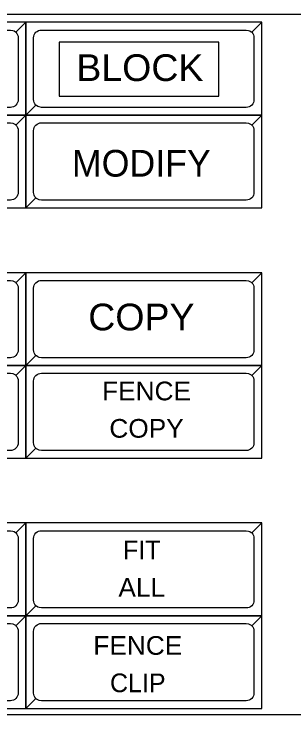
# Model space of a CAD drawing. Extents: x 16898 to 16911.6, y 15837.8 to 15842.
# Drawn here: x 16904.383 to 16905.198, y 15839.972 to 15842.012 of the extents above; entities that cross this region are included whole.
import ezdxf
from ezdxf.enums import TextEntityAlignment as Align

# ---------------------------------------------------------------- set-up
doc = ezdxf.new("R2010")
doc.units = 0
doc.header["$LTSCALE"] = 0.018
for name, color, linetype, lineweight in [('1', 7, 'Continuous', 25), ('2', 7, 'Continuous', 13), ('5', 7, 'Continuous', 13)]:
    doc.layers.add(name, color=color, linetype=linetype, lineweight=lineweight)

msp = doc.modelspace()

# ---------------------------------------------------------------- linework, layer by layer
at = {"layer": '1'}
for points in [[(16897.9955, 15839.9723), (16897.9955, 15842.0124), (16911.4764, 15842.0124), (16911.5674, 15841.9251), (16911.5674, 15840.0599), (16911.4764, 15839.9723)], [(16903.7314, 15841.7183), (16904.4178, 15841.7183), (16904.4178, 15841.9883), (16903.7314, 15841.9883)], [(16903.7314, 15841.7183), (16904.4178, 15841.7183), (16904.4178, 15841.9883), (16904.3887, 15841.9592), (16904.3915, 15841.9558), (16904.3936, 15841.9519), (16904.3948, 15841.9477), (16904.3953, 15841.9433), (16904.3953, 15841.7633), (16904.3948, 15841.7589), (16904.3936, 15841.7547), (16904.3915, 15841.7508), (16904.3887, 15841.7474), (16904.3887, 15841.7474), (16904.3853, 15841.7446), (16904.3814, 15841.7425), (16904.3772, 15841.7412), (16904.3728, 15841.7408), (16903.7764, 15841.7408), (16903.7698, 15841.7418), (16903.7658, 15841.7435), (16903.7621, 15841.7459), (16903.7605, 15841.7474)], [(16904.4178, 15841.9883), (16903.7314, 15841.9883), (16903.7314, 15841.7183), (16903.7605, 15841.7474), (16903.7577, 15841.7508), (16903.7556, 15841.7547), (16903.7543, 15841.7589), (16903.7539, 15841.7633), (16903.7539, 15841.9433), (16903.7543, 15841.9477), (16903.7556, 15841.9519), (16903.7577, 15841.9558), (16903.7605, 15841.9592), (16903.7605, 15841.9592), (16903.7639, 15841.962), (16903.7678, 15841.9641), (16903.772, 15841.9653), (16903.7764, 15841.9658), (16904.3728, 15841.9658), (16904.3794, 15841.9648), (16904.3834, 15841.9631), (16904.3871, 15841.9607), (16904.3887, 15841.9592)], [(16904.4178, 15841.7183), (16905.1042, 15841.7183), (16905.1042, 15841.9883), (16904.4178, 15841.9883)], [(16904.4178, 15841.7183), (16905.1042, 15841.7183), (16905.1042, 15841.9883), (16905.0751, 15841.9592), (16905.0779, 15841.9558), (16905.08, 15841.9519), (16905.0812, 15841.9477), (16905.0817, 15841.9433), (16905.0817, 15841.7633), (16905.0812, 15841.7589), (16905.08, 15841.7547), (16905.0779, 15841.7508), (16905.0751, 15841.7474), (16905.0751, 15841.7474), (16905.0717, 15841.7446), (16905.0678, 15841.7425), (16905.0636, 15841.7412), (16905.0592, 15841.7408), (16904.4628, 15841.7408), (16904.4562, 15841.7418), (16904.4522, 15841.7435), (16904.4485, 15841.7459), (16904.4469, 15841.7474)], [(16905.1042, 15841.9883), (16904.4178, 15841.9883), (16904.4178, 15841.7183), (16904.4469, 15841.7474), (16904.4441, 15841.7508), (16904.442, 15841.7547), (16904.4407, 15841.7589), (16904.4403, 15841.7633), (16904.4403, 15841.9433), (16904.4407, 15841.9477), (16904.442, 15841.9519), (16904.4441, 15841.9558), (16904.4469, 15841.9592), (16904.4469, 15841.9592), (16904.4503, 15841.962), (16904.4542, 15841.9641), (16904.4584, 15841.9653), (16904.4628, 15841.9658), (16905.0592, 15841.9658), (16905.0658, 15841.9648), (16905.0698, 15841.9631), (16905.0735, 15841.9607), (16905.0751, 15841.9592)], [(16903.7314, 15841.4483), (16904.4178, 15841.4483), (16904.4178, 15841.7183), (16903.7314, 15841.7183)], [(16903.7314, 15841.4483), (16904.4178, 15841.4483), (16904.4178, 15841.7183), (16904.3887, 15841.6892), (16904.3915, 15841.6858), (16904.3936, 15841.6819), (16904.3948, 15841.6777), (16904.3953, 15841.6733), (16904.3953, 15841.4933), (16904.3948, 15841.4889), (16904.3936, 15841.4847), (16904.3915, 15841.4808), (16904.3887, 15841.4774), (16904.3887, 15841.4774), (16904.3853, 15841.4746), (16904.3814, 15841.4725), (16904.3772, 15841.4712), (16904.3728, 15841.4708), (16903.7764, 15841.4708), (16903.7698, 15841.4718), (16903.7658, 15841.4735), (16903.7621, 15841.4759), (16903.7605, 15841.4774)], [(16904.4178, 15841.7183), (16903.7314, 15841.7183), (16903.7314, 15841.4483), (16903.7605, 15841.4774), (16903.7577, 15841.4808), (16903.7556, 15841.4847), (16903.7543, 15841.4889), (16903.7539, 15841.4933), (16903.7539, 15841.6733), (16903.7543, 15841.6777), (16903.7556, 15841.6819), (16903.7577, 15841.6858), (16903.7605, 15841.6892), (16903.7605, 15841.6892), (16903.7639, 15841.692), (16903.7678, 15841.6941), (16903.772, 15841.6953), (16903.7764, 15841.6958), (16904.3728, 15841.6958), (16904.3794, 15841.6948), (16904.3834, 15841.6931), (16904.3871, 15841.6907), (16904.3887, 15841.6892)], [(16904.4178, 15841.4483), (16905.1042, 15841.4483), (16905.1042, 15841.7183), (16904.4178, 15841.7183)], [(16904.4178, 15841.4483), (16905.1042, 15841.4483), (16905.1042, 15841.7183), (16905.0751, 15841.6892), (16905.0779, 15841.6858), (16905.08, 15841.6819), (16905.0812, 15841.6777), (16905.0817, 15841.6733), (16905.0817, 15841.4933), (16905.0812, 15841.4889), (16905.08, 15841.4847), (16905.0779, 15841.4808), (16905.0751, 15841.4774), (16905.0751, 15841.4774), (16905.0717, 15841.4746), (16905.0678, 15841.4725), (16905.0636, 15841.4712), (16905.0592, 15841.4708), (16904.4628, 15841.4708), (16904.4562, 15841.4718), (16904.4522, 15841.4735), (16904.4485, 15841.4759), (16904.4469, 15841.4774)], [(16905.1042, 15841.7183), (16904.4178, 15841.7183), (16904.4178, 15841.4483), (16904.4469, 15841.4774), (16904.4441, 15841.4808), (16904.442, 15841.4847), (16904.4407, 15841.4889), (16904.4403, 15841.4933), (16904.4403, 15841.6733), (16904.4407, 15841.6777), (16904.442, 15841.6819), (16904.4441, 15841.6858), (16904.4469, 15841.6892), (16904.4469, 15841.6892), (16904.4503, 15841.692), (16904.4542, 15841.6941), (16904.4584, 15841.6953), (16904.4628, 15841.6958), (16905.0592, 15841.6958), (16905.0658, 15841.6948), (16905.0698, 15841.6931), (16905.0735, 15841.6907), (16905.0751, 15841.6892)], [(16903.7314, 15840.9896), (16904.4178, 15840.9896), (16904.4178, 15841.2596), (16903.7314, 15841.2596)], [(16903.7314, 15840.9896), (16904.4178, 15840.9896), (16904.4178, 15841.2596), (16904.3887, 15841.2305), (16904.3915, 15841.2271), (16904.3936, 15841.2232), (16904.3948, 15841.219), (16904.3953, 15841.2146), (16904.3953, 15841.0346), (16904.3948, 15841.0302), (16904.3936, 15841.026), (16904.3915, 15841.0221), (16904.3887, 15841.0187), (16904.3887, 15841.0187), (16904.3853, 15841.0159), (16904.3814, 15841.0138), (16904.3772, 15841.0125), (16904.3728, 15841.0121), (16903.7764, 15841.0121), (16903.7698, 15841.0131), (16903.7658, 15841.0148), (16903.7621, 15841.0172), (16903.7605, 15841.0187)], [(16904.4178, 15841.2596), (16903.7314, 15841.2596), (16903.7314, 15840.9896), (16903.7605, 15841.0187), (16903.7577, 15841.0221), (16903.7556, 15841.026), (16903.7543, 15841.0302), (16903.7539, 15841.0346), (16903.7539, 15841.2146), (16903.7543, 15841.219), (16903.7556, 15841.2232), (16903.7577, 15841.2271), (16903.7605, 15841.2305), (16903.7605, 15841.2305), (16903.7639, 15841.2333), (16903.7678, 15841.2354), (16903.772, 15841.2366), (16903.7764, 15841.2371), (16904.3728, 15841.2371), (16904.3794, 15841.2361), (16904.3834, 15841.2344), (16904.3871, 15841.232), (16904.3887, 15841.2305)], [(16904.4178, 15840.9896), (16905.1042, 15840.9896), (16905.1042, 15841.2596), (16904.4178, 15841.2596)], [(16904.4178, 15840.9896), (16905.1042, 15840.9896), (16905.1042, 15841.2596), (16905.0751, 15841.2305), (16905.0779, 15841.2271), (16905.08, 15841.2232), (16905.0812, 15841.219), (16905.0817, 15841.2146), (16905.0817, 15841.0346), (16905.0812, 15841.0302), (16905.08, 15841.026), (16905.0779, 15841.0221), (16905.0751, 15841.0187), (16905.0751, 15841.0187), (16905.0717, 15841.0159), (16905.0678, 15841.0138), (16905.0636, 15841.0125), (16905.0592, 15841.0121), (16904.4628, 15841.0121), (16904.4562, 15841.0131), (16904.4522, 15841.0148), (16904.4485, 15841.0172), (16904.4469, 15841.0187)], [(16905.1042, 15841.2596), (16904.4178, 15841.2596), (16904.4178, 15840.9896), (16904.4469, 15841.0187), (16904.4441, 15841.0221), (16904.442, 15841.026), (16904.4407, 15841.0302), (16904.4403, 15841.0346), (16904.4403, 15841.2146), (16904.4407, 15841.219), (16904.442, 15841.2232), (16904.4441, 15841.2271), (16904.4469, 15841.2305), (16904.4469, 15841.2305), (16904.4503, 15841.2333), (16904.4542, 15841.2354), (16904.4584, 15841.2366), (16904.4628, 15841.2371), (16905.0592, 15841.2371), (16905.0658, 15841.2361), (16905.0698, 15841.2344), (16905.0735, 15841.232), (16905.0751, 15841.2305)], [(16903.7314, 15840.7196), (16904.4178, 15840.7196), (16904.4178, 15840.9896), (16903.7314, 15840.9896)], [(16903.7314, 15840.7196), (16904.4178, 15840.7196), (16904.4178, 15840.9896), (16904.3887, 15840.9605), (16904.3915, 15840.9571), (16904.3936, 15840.9532), (16904.3948, 15840.949), (16904.3953, 15840.9446), (16904.3953, 15840.7646), (16904.3948, 15840.7602), (16904.3936, 15840.756), (16904.3915, 15840.7521), (16904.3887, 15840.7487), (16904.3887, 15840.7487), (16904.3853, 15840.7459), (16904.3814, 15840.7438), (16904.3772, 15840.7425), (16904.3728, 15840.7421), (16903.7764, 15840.7421), (16903.7698, 15840.7431), (16903.7658, 15840.7448), (16903.7621, 15840.7472), (16903.7605, 15840.7487)], [(16904.4178, 15840.9896), (16903.7314, 15840.9896), (16903.7314, 15840.7196), (16903.7605, 15840.7487), (16903.7577, 15840.7521), (16903.7556, 15840.756), (16903.7543, 15840.7602), (16903.7539, 15840.7646), (16903.7539, 15840.9446), (16903.7543, 15840.949), (16903.7556, 15840.9532), (16903.7577, 15840.9571), (16903.7605, 15840.9605), (16903.7605, 15840.9605), (16903.7639, 15840.9633), (16903.7678, 15840.9654), (16903.772, 15840.9666), (16903.7764, 15840.9671), (16904.3728, 15840.9671), (16904.3794, 15840.9661), (16904.3834, 15840.9644), (16904.3871, 15840.962), (16904.3887, 15840.9605)], [(16904.4178, 15840.7196), (16905.1042, 15840.7196), (16905.1042, 15840.9896), (16904.4178, 15840.9896)], [(16904.4178, 15840.7196), (16905.1042, 15840.7196), (16905.1042, 15840.9896), (16905.0751, 15840.9605), (16905.0779, 15840.9571), (16905.08, 15840.9532), (16905.0812, 15840.949), (16905.0817, 15840.9446), (16905.0817, 15840.7646), (16905.0812, 15840.7602), (16905.08, 15840.756), (16905.0779, 15840.7521), (16905.0751, 15840.7487), (16905.0751, 15840.7487), (16905.0717, 15840.7459), (16905.0678, 15840.7438), (16905.0636, 15840.7425), (16905.0592, 15840.7421), (16904.4628, 15840.7421), (16904.4562, 15840.7431), (16904.4522, 15840.7448), (16904.4485, 15840.7472), (16904.4469, 15840.7487)], [(16905.1042, 15840.9896), (16904.4178, 15840.9896), (16904.4178, 15840.7196), (16904.4469, 15840.7487), (16904.4441, 15840.7521), (16904.442, 15840.756), (16904.4407, 15840.7602), (16904.4403, 15840.7646), (16904.4403, 15840.9446), (16904.4407, 15840.949), (16904.442, 15840.9532), (16904.4441, 15840.9571), (16904.4469, 15840.9605), (16904.4469, 15840.9605), (16904.4503, 15840.9633), (16904.4542, 15840.9654), (16904.4584, 15840.9666), (16904.4628, 15840.9671), (16905.0592, 15840.9671), (16905.0658, 15840.9661), (16905.0698, 15840.9644), (16905.0735, 15840.962), (16905.0751, 15840.9605)], [(16903.7314, 15840.2612), (16904.4178, 15840.2612), (16904.4178, 15840.5312), (16903.7314, 15840.5312)], [(16903.7314, 15840.2612), (16904.4178, 15840.2612), (16904.4178, 15840.5312), (16904.3887, 15840.5021), (16904.3915, 15840.4987), (16904.3936, 15840.4948), (16904.3948, 15840.4906), (16904.3953, 15840.4862), (16904.3953, 15840.3062), (16904.3948, 15840.3018), (16904.3936, 15840.2976), (16904.3915, 15840.2937), (16904.3887, 15840.2903), (16904.3887, 15840.2903), (16904.3853, 15840.2875), (16904.3814, 15840.2854), (16904.3772, 15840.2841), (16904.3728, 15840.2837), (16903.7764, 15840.2837), (16903.7698, 15840.2847), (16903.7658, 15840.2864), (16903.7621, 15840.2888), (16903.7605, 15840.2903)], [(16904.4178, 15840.5312), (16903.7314, 15840.5312), (16903.7314, 15840.2612), (16903.7605, 15840.2903), (16903.7577, 15840.2937), (16903.7556, 15840.2976), (16903.7543, 15840.3018), (16903.7539, 15840.3062), (16903.7539, 15840.4862), (16903.7543, 15840.4906), (16903.7556, 15840.4948), (16903.7577, 15840.4987), (16903.7605, 15840.5021), (16903.7605, 15840.5021), (16903.7639, 15840.5049), (16903.7678, 15840.507), (16903.772, 15840.5082), (16903.7764, 15840.5087), (16904.3728, 15840.5087), (16904.3794, 15840.5077), (16904.3834, 15840.506), (16904.3871, 15840.5036), (16904.3887, 15840.5021)], [(16904.4178, 15840.2612), (16905.1042, 15840.2612), (16905.1042, 15840.5312), (16904.4178, 15840.5312)], [(16904.4178, 15840.2612), (16905.1042, 15840.2612), (16905.1042, 15840.5312), (16905.0751, 15840.5021), (16905.0779, 15840.4987), (16905.08, 15840.4948), (16905.0812, 15840.4906), (16905.0817, 15840.4862), (16905.0817, 15840.3062), (16905.0812, 15840.3018), (16905.08, 15840.2976), (16905.0779, 15840.2937), (16905.0751, 15840.2903), (16905.0751, 15840.2903), (16905.0717, 15840.2875), (16905.0678, 15840.2854), (16905.0636, 15840.2841), (16905.0592, 15840.2837), (16904.4628, 15840.2837), (16904.4562, 15840.2847), (16904.4522, 15840.2864), (16904.4485, 15840.2888), (16904.4469, 15840.2903)], [(16905.1042, 15840.5312), (16904.4178, 15840.5312), (16904.4178, 15840.2612), (16904.4469, 15840.2903), (16904.4441, 15840.2937), (16904.442, 15840.2976), (16904.4407, 15840.3018), (16904.4403, 15840.3062), (16904.4403, 15840.4862), (16904.4407, 15840.4906), (16904.442, 15840.4948), (16904.4441, 15840.4987), (16904.4469, 15840.5021), (16904.4469, 15840.5021), (16904.4503, 15840.5049), (16904.4542, 15840.507), (16904.4584, 15840.5082), (16904.4628, 15840.5087), (16905.0592, 15840.5087), (16905.0658, 15840.5077), (16905.0698, 15840.506), (16905.0735, 15840.5036), (16905.0751, 15840.5021)], [(16903.7314, 15839.9912), (16904.4178, 15839.9912), (16904.4178, 15840.2612), (16903.7314, 15840.2612)], [(16903.7314, 15839.9912), (16904.4178, 15839.9912), (16904.4178, 15840.2612), (16904.3887, 15840.2321), (16904.3915, 15840.2287), (16904.3936, 15840.2248), (16904.3948, 15840.2206), (16904.3953, 15840.2162), (16904.3953, 15840.0362), (16904.3948, 15840.0318), (16904.3936, 15840.0276), (16904.3915, 15840.0237), (16904.3887, 15840.0203), (16904.3887, 15840.0203), (16904.3853, 15840.0175), (16904.3814, 15840.0154), (16904.3772, 15840.0141), (16904.3728, 15840.0137), (16903.7764, 15840.0137), (16903.7698, 15840.0147), (16903.7658, 15840.0164), (16903.7621, 15840.0188), (16903.7605, 15840.0203)], [(16904.4178, 15840.2612), (16903.7314, 15840.2612), (16903.7314, 15839.9912), (16903.7605, 15840.0203), (16903.7577, 15840.0237), (16903.7556, 15840.0276), (16903.7543, 15840.0318), (16903.7539, 15840.0362), (16903.7539, 15840.2162), (16903.7543, 15840.2206), (16903.7556, 15840.2248), (16903.7577, 15840.2287), (16903.7605, 15840.2321), (16903.7605, 15840.2321), (16903.7639, 15840.2349), (16903.7678, 15840.237), (16903.772, 15840.2382), (16903.7764, 15840.2387), (16904.3728, 15840.2387), (16904.3794, 15840.2377), (16904.3834, 15840.236), (16904.3871, 15840.2336), (16904.3887, 15840.2321)], [(16904.4178, 15839.9912), (16905.1042, 15839.9912), (16905.1042, 15840.2612), (16904.4178, 15840.2612)], [(16904.4178, 15839.9912), (16905.1042, 15839.9912), (16905.1042, 15840.2612), (16905.0751, 15840.2321), (16905.0779, 15840.2287), (16905.08, 15840.2248), (16905.0812, 15840.2206), (16905.0817, 15840.2162), (16905.0817, 15840.0362), (16905.0812, 15840.0318), (16905.08, 15840.0276), (16905.0779, 15840.0237), (16905.0751, 15840.0203), (16905.0751, 15840.0203), (16905.0717, 15840.0175), (16905.0678, 15840.0154), (16905.0636, 15840.0141), (16905.0592, 15840.0137), (16904.4628, 15840.0137), (16904.4562, 15840.0147), (16904.4522, 15840.0164), (16904.4485, 15840.0188), (16904.4469, 15840.0203)], [(16905.1042, 15840.2612), (16904.4178, 15840.2612), (16904.4178, 15839.9912), (16904.4469, 15840.0203), (16904.4441, 15840.0237), (16904.442, 15840.0276), (16904.4407, 15840.0318), (16904.4403, 15840.0362), (16904.4403, 15840.2162), (16904.4407, 15840.2206), (16904.442, 15840.2248), (16904.4441, 15840.2287), (16904.4469, 15840.2321), (16904.4469, 15840.2321), (16904.4503, 15840.2349), (16904.4542, 15840.237), (16904.4584, 15840.2382), (16904.4628, 15840.2387), (16905.0592, 15840.2387), (16905.0658, 15840.2377), (16905.0698, 15840.236), (16905.0735, 15840.2336), (16905.0751, 15840.2321)]]:
    msp.add_lwpolyline(points, close=True, dxfattribs=at)
at = {"layer": '2'}
msp.add_lwpolyline([(16897.9955, 15839.9723), (16897.9955, 15842.0124), (16911.4764, 15842.0124), (16911.5674, 15841.9251), (16911.5674, 15840.0599), (16911.4764, 15839.9723)], close=True, dxfattribs=at)
at = {"layer": '5', "lineweight": 25}
msp.add_lwpolyline([(16904.5145, 15841.7736), (16904.9797, 15841.7736), (16904.9797, 15841.93), (16904.5145, 15841.93)], close=True, dxfattribs=at)

# ---------------------------------------------------------------- texts
at = {"layer": '5', "width": 1.05}
for s, height, p in [('BLOCK', 0.07772, (16904.7495, 15841.8174)), ('COPY', 0.07772, (16904.7539, 15841.0917)), ('FENCE', 0.0544, (16904.7689, 15840.8881)), ('COPY', 0.0544, (16904.7689, 15840.7793)), ('ALL', 0.0544, (16904.755, 15840.3164)), ('FENCE', 0.0544, (16904.7435, 15840.1474))]:
    msp.add_text(s, height=height, dxfattribs=at).set_placement(p, align=Align.CENTER)
at = {"layer": '5'}
for s, height, p in [('MODIFY', 0.07772, (16904.7538, 15841.5392)), ('FIT', 0.0544, (16904.755, 15840.4251)), ('CLIP', 0.0544, (16904.7435, 15840.0386))]:
    msp.add_text(s, height=height, dxfattribs=at).set_placement(p, align=Align.CENTER)

doc.saveas('drawing.dxf')
